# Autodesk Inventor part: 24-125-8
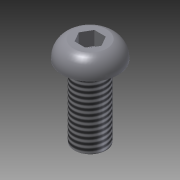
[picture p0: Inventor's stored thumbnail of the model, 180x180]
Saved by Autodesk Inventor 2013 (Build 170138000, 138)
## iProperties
Created: 2004-10
Part Number: 24-125-8
Material: Stahl (hohe Festigk., niedr. Legier.)
Document SubType Name: Modeling
Designer: Autodesk, Inc.
Manufacturer: Standard
Standards Organization: Custom
Description: SCREW, PARKER IPS, BUTTON HEAD, M8X25
Catalog Web Link: http://www.parker.com/ead/cm1.asp?cmid=809
Vendor: PARKER IPS
Mass: 10.8823 g
Surface Area: 9.37524 cm^2
Volume: 1.38805 cm^3
Density: 7.84 g/cm^3
CAGE: 1LJX3
Dept. ID: Product Design
Description #2: ---
Finish #1: ---
Finish #2: ---
Material ID: ---
Project Number: ---
Author: Autodesk, Inc.
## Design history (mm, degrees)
derived "2X-YYY-ZZ IPS Screws.ipt"
body "Solid1"
tag "TaggingFeature2"
feature "Solid1::2X-YYY-ZZ IPS Screws.ipt" dims "ScaleForDerivedMember" = 10
